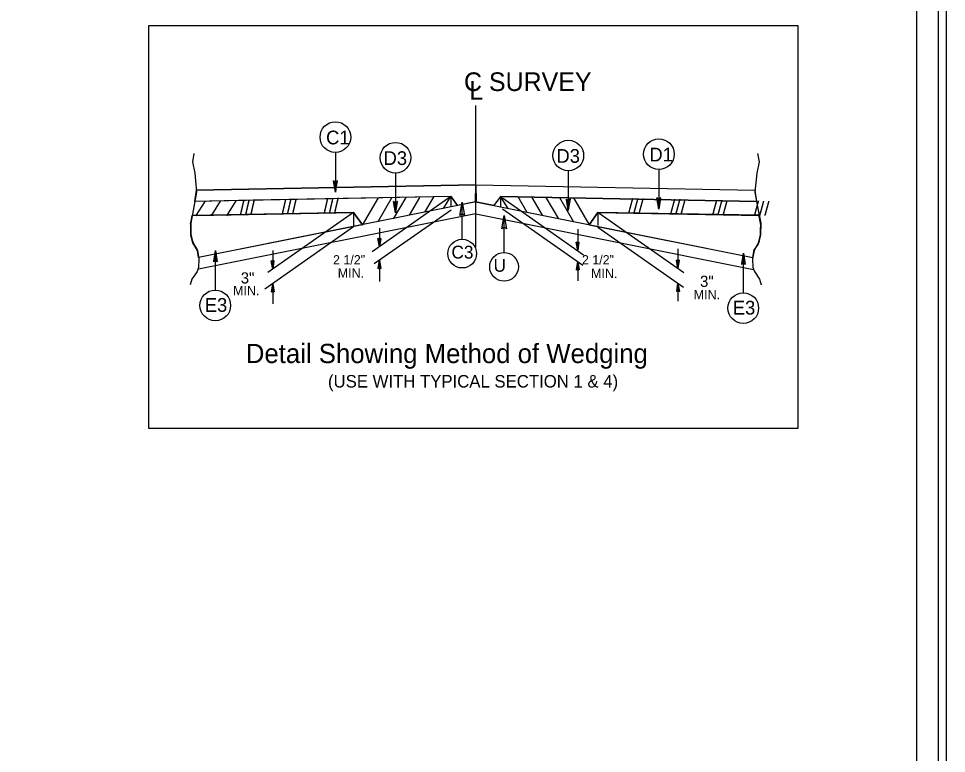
# Model space of a CAD drawing. Extents: x 981824 to 982276, y 44828 to 45204.
# Drawn here: x 982186.38 to 982229.08, y 45122.91 to 45156.74 of the extents above; entities that cross this region are included whole.
import ezdxf

# ---------------------------------------------------------------- set-up
doc = ezdxf.new("R2010")
doc.units = 0
for name, color, linetype in [('Old_Level_1', 7, 'Continuous'), ('Old_Level_11', 7, 'Continuous'), ('Old_Level_18', 7, 'Continuous'), ('Old_Level_19', 7, 'Continuous'), ('Old_Level_2', 7, 'Continuous'), ('Old_Level_20', 7, 'Continuous'), ('Old_Level_21', 7, 'Continuous'), ('Old_Level_3', 7, 'Continuous'), ('Old_Level_50', 7, 'Continuous'), ('Old_Level_51', 7, 'Continuous'), ('Prop Dimension Text', 7, 'Continuous'), ('Prop Roadway Profile Bench Mark Info Text', 7, 'Continuous')]:
    doc.layers.add(name, color=color, linetype=linetype)

msp = doc.modelspace()

# ---------------------------------------------------------------- linework, layer by layer
at = {"layer": 'Old_Level_1'}
for p, q in [((982200.96, 45148.752), (982200.871, 45149.272)), ((982200.96, 45149.201), (982200.871, 45149.272)), ((982200.96, 45148.752), (982200.882, 45149.262)), ((982200.894, 45149.251), (982200.96, 45148.752)), ((982200.96, 45148.752), (982200.909, 45149.24)), ((982200.923, 45149.233), (982200.96, 45148.752)), ((982200.96, 45148.752), (982200.934, 45149.222)), ((982200.948, 45149.213), (982200.96, 45148.752)), ((982200.96, 45148.752), (982201.053, 45149.272)), ((982201.053, 45149.272), (982200.96, 45149.201)), ((982201.035, 45149.262), (982200.96, 45148.752)), ((982200.96, 45148.752), (982201.026, 45149.251)), ((982201.012, 45149.24), (982200.96, 45148.752)), ((982200.96, 45148.752), (982200.997, 45149.233)), ((982200.983, 45149.222), (982200.96, 45148.752)), ((982200.96, 45148.752), (982200.975, 45149.213)), ((982200.96, 45149.201), (982200.96, 45148.752)), ((982194.55, 45147.673), (982194.962, 45148.326)), ((982195.268, 45147.688), (982195.68, 45148.34)), ((982195.962, 45147.661), (982196.399, 45148.354)), ((982202.924, 45148.484), (982202.193, 45147.234)), ((982203.565, 45148.497), (982202.918, 45147.388)), ((982204.2, 45148.51), (982203.62, 45147.515)), ((982203.726, 45147.803), (982203.637, 45148.323)), ((982203.726, 45148.252), (982203.637, 45148.323)), ((982203.726, 45147.803), (982203.648, 45148.313)), ((982203.66, 45148.302), (982203.726, 45147.803)), ((982203.726, 45147.803), (982203.675, 45148.291)), ((982203.689, 45148.284), (982203.726, 45147.803)), ((982203.726, 45147.803), (982203.7, 45148.273)), ((982203.714, 45148.264), (982203.726, 45147.803)), ((982203.726, 45147.803), (982203.819, 45148.323)), ((982203.819, 45148.323), (982203.726, 45148.252)), ((982203.801, 45148.313), (982203.726, 45147.803)), ((982203.726, 45147.803), (982203.792, 45148.302)), ((982203.778, 45148.291), (982203.726, 45147.803)), ((982203.726, 45147.803), (982203.763, 45148.284)), ((982203.749, 45148.273), (982203.726, 45147.803)), ((982203.726, 45147.803), (982203.741, 45148.264)), ((982203.726, 45148.252), (982203.726, 45147.803)), ((982204.839, 45148.508), (982204.358, 45147.684)), ((982205.484, 45148.542), (982205.065, 45147.822)), ((982208.655, 45148.483), (982212.386, 45145.87)), ((982209.357, 45148.542), (982209.776, 45147.822)), ((982210.003, 45148.508), (982210.483, 45147.684)), ((982210.643, 45148.51), (982211.222, 45147.515)), ((982211.277, 45148.497), (982211.923, 45147.388)), ((982211.68, 45147.904), (982211.591, 45148.424)), ((982211.68, 45148.353), (982211.591, 45148.424)), ((982211.68, 45147.904), (982211.602, 45148.414)), ((982211.614, 45148.403), (982211.68, 45147.904)), ((982211.68, 45147.904), (982211.629, 45148.392)), ((982211.643, 45148.385), (982211.68, 45147.904)), ((982211.68, 45147.904), (982211.654, 45148.374)), ((982211.668, 45148.365), (982211.68, 45147.904)), ((982211.68, 45147.904), (982211.773, 45148.424)), ((982211.773, 45148.424), (982211.68, 45148.353)), ((982211.755, 45148.414), (982211.68, 45147.904)), ((982211.68, 45147.904), (982211.746, 45148.403)), ((982211.732, 45148.392), (982211.68, 45147.904)), ((982211.68, 45147.904), (982211.717, 45148.385)), ((982211.703, 45148.374), (982211.68, 45147.904)), ((982211.68, 45147.904), (982211.695, 45148.365)), ((982211.68, 45148.353), (982211.68, 45147.904)), ((982211.919, 45148.484), (982212.638, 45147.251)), ((982215.847, 45147.967), (982215.758, 45148.487)), ((982215.847, 45148.416), (982215.758, 45148.487)), ((982215.847, 45147.967), (982215.769, 45148.477)), ((982215.781, 45148.466), (982215.847, 45147.967)), ((982215.847, 45147.967), (982215.796, 45148.455)), ((982215.81, 45148.448), (982215.847, 45147.967)), ((982215.847, 45147.967), (982215.821, 45148.437)), ((982215.835, 45148.428), (982215.847, 45147.967)), ((982215.847, 45147.967), (982215.94, 45148.487)), ((982215.94, 45148.487), (982215.847, 45148.416)), ((982215.922, 45148.477), (982215.847, 45147.967)), ((982215.847, 45147.967), (982215.913, 45148.466)), ((982215.899, 45148.455), (982215.847, 45147.967)), ((982215.847, 45147.967), (982215.884, 45148.448)), ((982215.87, 45148.437), (982215.847, 45147.967)), ((982215.847, 45147.967), (982215.862, 45148.428)), ((982215.847, 45148.416), (982215.847, 45147.967)), ((982201.799, 45147.818), (982194.373, 45147.67)), ((982194.55, 45147.673), (982201.799, 45147.818)), ((982201.799, 45147.818), (982197.856, 45145.057)), ((982202.204, 45147.25), (982201.799, 45147.818)), ((982201.799, 45147.818), (982201.799, 45147.169)), ((982201.799, 45147.818), (982202.203, 45147.251)), ((982206.287, 45147.923), (982202.744, 45145.442)), ((982208.651, 45147.975), (982212.344, 45145.39)), ((982213.042, 45147.818), (982212.638, 45147.251)), ((982212.639, 45147.251), (982213.042, 45147.818)), ((982213.042, 45147.818), (982220.467, 45147.67)), ((982213.042, 45147.818), (982213.042, 45147.215)), ((982218.339, 45147.712), (982213.042, 45147.818)), ((982213.102, 45147.775), (982216.991, 45145.052)), ((982220.467, 45147.67), (982218.339, 45147.712)), ((982200.507, 45146.912), (982194.668, 45145.745)), ((982201.797, 45147.15), (982197.721, 45144.281)), ((982201.799, 45147.171), (982200.507, 45146.912)), ((982202.203, 45147.251), (982201.799, 45147.171)), ((982202.988, 45147.098), (982202.988, 45146.238)), ((982212.113, 45147.05), (982212.113, 45146.063)), ((982212.638, 45147.251), (982214.335, 45146.912)), ((982213.042, 45147.137), (982216.984, 45144.375)), ((982214.335, 45146.912), (982220.174, 45145.745)), ((982202.988, 45146.238), (982202.922, 45146.615)), ((982202.988, 45146.567), (982202.922, 45146.615)), ((982202.988, 45146.238), (982202.932, 45146.608)), ((982202.941, 45146.602), (982202.988, 45146.238)), ((982202.988, 45146.238), (982202.951, 45146.594)), ((982202.96, 45146.588), (982202.988, 45146.238)), ((982202.988, 45146.238), (982202.969, 45146.58)), ((982202.979, 45146.574), (982202.988, 45146.238)), ((982202.988, 45146.238), (982203.055, 45146.615)), ((982203.055, 45146.615), (982202.988, 45146.567)), ((982203.047, 45146.608), (982202.988, 45146.238)), ((982202.988, 45146.238), (982203.036, 45146.602)), ((982203.027, 45146.594), (982202.988, 45146.238)), ((982202.988, 45146.238), (982203.016, 45146.588)), ((982203.008, 45146.58), (982202.988, 45146.238)), ((982202.988, 45146.238), (982202.998, 45146.574)), ((982202.988, 45146.567), (982202.988, 45146.238)), ((982212.113, 45146.063), (982212.047, 45146.442)), ((982212.113, 45146.391), (982212.047, 45146.442)), ((982212.113, 45146.063), (982212.056, 45146.433)), ((982212.066, 45146.426), (982212.113, 45146.063)), ((982212.113, 45146.063), (982212.181, 45146.442)), ((982212.181, 45146.442), (982212.113, 45146.391)), ((982212.17, 45146.433), (982212.113, 45146.063)), ((982212.113, 45146.063), (982212.159, 45146.426)), ((982195.437, 45146.064), (982195.345, 45145.545)), ((982195.437, 45146.064), (982195.357, 45145.555)), ((982195.37, 45145.567), (982195.437, 45146.064)), ((982195.437, 45146.064), (982195.382, 45145.573)), ((982195.394, 45145.584), (982195.437, 45146.064)), ((982195.437, 45146.064), (982195.409, 45145.591)), ((982195.423, 45145.602), (982195.437, 45146.064)), ((982195.437, 45146.064), (982195.526, 45145.545)), ((982195.512, 45145.555), (982195.437, 45146.064)), ((982195.437, 45146.064), (982195.501, 45145.567)), ((982195.489, 45145.573), (982195.437, 45146.064)), ((982195.437, 45146.064), (982195.475, 45145.584)), ((982195.46, 45145.591), (982195.437, 45146.064)), ((982195.437, 45146.064), (982195.449, 45145.602)), ((982195.437, 45145.613), (982195.437, 45146.064)), ((982198.079, 45146.07), (982198.079, 45145.211)), ((982212.113, 45146.063), (982212.075, 45146.419)), ((982212.085, 45146.413), (982212.113, 45146.063)), ((982212.113, 45146.063), (982212.095, 45146.406)), ((982212.103, 45146.398), (982212.113, 45146.063)), ((982212.15, 45146.419), (982212.113, 45146.063)), ((982212.113, 45146.063), (982212.14, 45146.413)), ((982212.131, 45146.406), (982212.113, 45146.063)), ((982212.113, 45146.063), (982212.123, 45146.398)), ((982212.113, 45146.391), (982212.113, 45146.063)), ((982216.724, 45146.133), (982216.724, 45145.24)), ((982195.437, 45145.613), (982195.345, 45145.545)), ((982195.526, 45145.545), (982195.437, 45145.613)), ((982198.079, 45145.211), (982198.011, 45145.59)), ((982198.079, 45145.54), (982198.011, 45145.59)), ((982198.079, 45145.211), (982198.02, 45145.583)), ((982198.031, 45145.576), (982198.079, 45145.211)), ((982198.079, 45145.211), (982198.041, 45145.569)), ((982198.079, 45145.211), (982198.146, 45145.59)), ((982198.146, 45145.59), (982198.079, 45145.54)), ((982198.136, 45145.583), (982198.079, 45145.211)), ((982198.079, 45145.211), (982198.127, 45145.576)), ((982198.117, 45145.569), (982198.079, 45145.211)), ((982202.988, 45145.614), (982202.922, 45145.234)), ((982202.932, 45145.242), (982202.988, 45145.614)), ((982202.988, 45145.614), (982202.941, 45145.25)), ((982202.951, 45145.257), (982202.988, 45145.614)), ((982202.988, 45145.614), (982202.96, 45145.263)), ((982202.969, 45145.27), (982202.988, 45145.614)), ((982202.988, 45145.614), (982202.979, 45145.276)), ((982202.988, 45145.614), (982202.988, 45144.642)), ((982202.988, 45145.614), (982203.055, 45145.234)), ((982202.988, 45145.285), (982202.988, 45145.614)), ((982202.998, 45145.276), (982202.988, 45145.614)), ((982202.988, 45145.614), (982203.008, 45145.27)), ((982203.016, 45145.263), (982202.988, 45145.614)), ((982202.988, 45145.614), (982203.027, 45145.257)), ((982203.036, 45145.25), (982202.988, 45145.614)), ((982202.988, 45145.614), (982203.047, 45145.242)), ((982216.724, 45145.24), (982216.657, 45145.617)), ((982216.724, 45145.569), (982216.657, 45145.617)), ((982216.724, 45145.24), (982216.666, 45145.61)), ((982216.675, 45145.604), (982216.724, 45145.24)), ((982216.724, 45145.24), (982216.686, 45145.597)), ((982216.694, 45145.59), (982216.724, 45145.24)), ((982216.724, 45145.24), (982216.703, 45145.583)), ((982216.713, 45145.576), (982216.724, 45145.24)), ((982216.724, 45145.24), (982216.791, 45145.617)), ((982216.791, 45145.617), (982216.724, 45145.569)), ((982216.78, 45145.61), (982216.724, 45145.24)), ((982216.724, 45145.24), (982216.771, 45145.604)), ((982216.762, 45145.597), (982216.724, 45145.24)), ((982216.724, 45145.24), (982216.751, 45145.59)), ((982216.743, 45145.583), (982216.724, 45145.24)), ((982216.724, 45145.24), (982216.734, 45145.576)), ((982216.724, 45145.569), (982216.724, 45145.24)), ((982219.735, 45145.939), (982219.643, 45145.42)), ((982219.735, 45145.939), (982219.655, 45145.43)), ((982219.668, 45145.442), (982219.735, 45145.939)), ((982219.735, 45145.939), (982219.68, 45145.448)), ((982219.692, 45145.459), (982219.735, 45145.939)), ((982219.735, 45145.939), (982219.707, 45145.466)), ((982219.721, 45145.477), (982219.735, 45145.939)), ((982219.735, 45145.939), (982219.824, 45145.42)), ((982219.81, 45145.43), (982219.735, 45145.939)), ((982219.735, 45145.939), (982219.799, 45145.442)), ((982219.787, 45145.448), (982219.735, 45145.939)), ((982219.735, 45145.939), (982219.773, 45145.459)), ((982219.758, 45145.466), (982219.735, 45145.939)), ((982219.735, 45145.939), (982219.747, 45145.477)), ((982219.735, 45145.488), (982219.735, 45145.939)), ((982198.051, 45145.562), (982198.079, 45145.211)), ((982198.079, 45145.211), (982198.059, 45145.554)), ((982198.069, 45145.548), (982198.079, 45145.211)), ((982198.079, 45145.211), (982198.107, 45145.562)), ((982198.098, 45145.554), (982198.079, 45145.211)), ((982198.079, 45145.211), (982198.088, 45145.548)), ((982198.079, 45145.54), (982198.079, 45145.211)), ((982202.922, 45145.234), (982202.988, 45145.285)), ((982202.988, 45145.285), (982203.055, 45145.234)), ((982212.113, 45145.553), (982212.047, 45145.174)), ((982212.047, 45145.174), (982212.113, 45145.224)), ((982212.056, 45145.182), (982212.113, 45145.553)), ((982212.113, 45145.553), (982212.066, 45145.188)), ((982212.075, 45145.196), (982212.113, 45145.553)), ((982212.113, 45145.553), (982212.085, 45145.201)), ((982212.095, 45145.209), (982212.113, 45145.553)), ((982212.113, 45145.553), (982212.103, 45145.216)), ((982212.113, 45145.553), (982212.113, 45144.669)), ((982212.113, 45145.553), (982212.181, 45145.174)), ((982212.113, 45145.224), (982212.113, 45145.553)), ((982212.123, 45145.216), (982212.113, 45145.553)), ((982212.113, 45145.553), (982212.131, 45145.209)), ((982212.14, 45145.201), (982212.113, 45145.553)), ((982212.113, 45145.553), (982212.15, 45145.196)), ((982212.159, 45145.188), (982212.113, 45145.553)), ((982212.113, 45145.553), (982212.17, 45145.182)), ((982212.113, 45145.224), (982212.181, 45145.174)), ((982219.735, 45145.488), (982219.643, 45145.42)), ((982219.824, 45145.42), (982219.735, 45145.488)), ((982198.079, 45144.532), (982198.011, 45144.155)), ((982198.022, 45144.161), (982198.079, 45144.532)), ((982198.079, 45144.532), (982198.031, 45144.169)), ((982198.041, 45144.175), (982198.079, 45144.532)), ((982198.079, 45144.532), (982198.051, 45144.183)), ((982198.059, 45144.189), (982198.079, 45144.532)), ((982198.079, 45144.532), (982198.069, 45144.196)), ((982198.079, 45144.532), (982198.079, 45143.614)), ((982198.079, 45144.532), (982198.146, 45144.155)), ((982198.079, 45144.202), (982198.079, 45144.532)), ((982198.088, 45144.196), (982198.079, 45144.532)), ((982198.079, 45144.532), (982198.098, 45144.189)), ((982198.107, 45144.183), (982198.079, 45144.532)), ((982198.079, 45144.532), (982198.117, 45144.175)), ((982198.127, 45144.169), (982198.079, 45144.532)), ((982198.079, 45144.532), (982198.136, 45144.161)), ((982216.724, 45144.558), (982216.657, 45144.18)), ((982216.666, 45144.186), (982216.724, 45144.558)), ((982216.724, 45144.558), (982216.675, 45144.194)), ((982216.686, 45144.201), (982216.724, 45144.558)), ((982216.724, 45144.558), (982216.694, 45144.21)), ((982216.703, 45144.215), (982216.724, 45144.558)), ((982216.724, 45144.558), (982216.713, 45144.222)), ((982216.724, 45144.558), (982216.724, 45143.73)), ((982216.724, 45144.558), (982216.791, 45144.18)), ((982216.724, 45144.23), (982216.724, 45144.558)), ((982216.734, 45144.222), (982216.724, 45144.558)), ((982216.724, 45144.558), (982216.743, 45144.215)), ((982216.751, 45144.21), (982216.724, 45144.558)), ((982216.724, 45144.558), (982216.762, 45144.201)), ((982216.771, 45144.194), (982216.724, 45144.558)), ((982216.724, 45144.558), (982216.78, 45144.186)), ((982198.011, 45144.155), (982198.079, 45144.202)), ((982198.079, 45144.202), (982198.146, 45144.155)), ((982216.657, 45144.18), (982216.724, 45144.23)), ((982216.724, 45144.23), (982216.791, 45144.18))]:
    msp.add_line(p, q, dxfattribs=at)
for points in [[(982194.668, 45145.745), (982194.612, 45146.059), (982194.406, 45146.414), (982194.316, 45146.767), (982194.305, 45147.326), (982194.373, 45147.67)], [(982220.174, 45145.745), (982220.23, 45146.059), (982220.435, 45146.414), (982220.527, 45146.767), (982220.537, 45147.326), (982220.467, 45147.67)]]:
    msp.add_lwpolyline(points, dxfattribs=at)
at = {"layer": 'Old_Level_11'}
for p, q in [((982194.572, 45148.833), (982207.42, 45149.089)), ((982207.42, 45149.089), (982220.27, 45148.833)), ((982207.422, 45149.089), (982220.27, 45148.833)), ((982220.27, 45148.833), (982220.344, 45148.316)), ((982206.293, 45148.551), (982194.499, 45148.316)), ((982206.582, 45148.129), (982206.293, 45148.551)), ((982207.402, 45148.298), (982206.582, 45148.129)), ((982208.26, 45148.129), (982207.402, 45148.298)), ((982208.557, 45148.551), (982208.26, 45148.129)), ((982208.557, 45148.551), (982220.344, 45148.316))]:
    msp.add_line(p, q, dxfattribs=at)
for points in [[(982192.377, 45156.415), (982222.235, 45156.415), (982222.235, 45137.875), (982192.377, 45137.875)], [(982206.692, 45147.677), (982206.798, 45148.289), (982206.907, 45147.673), (982206.798, 45147.751)], [(982208.619, 45147.068), (982208.724, 45147.68), (982208.833, 45147.064), (982208.724, 45147.142)]]:
    msp.add_lwpolyline(points, close=True, dxfattribs=at)
at = {"layer": 'Old_Level_18'}
msp.add_lwpolyline([(982227.72, 45175.969), (982107.72, 45175.969), (982107.72, 45091.969), (982227.72, 45091.969)], close=True, dxfattribs=at)
at = {"layer": 'Old_Level_19'}
for points in [[(982194.572, 45148.833), (982207.42, 45149.089), (982207.439, 45148.298), (982206.582, 45148.129), (982206.293, 45148.551), (982197.172, 45148.374), (982194.499, 45148.316)], [(982207.42, 45149.089), (982220.27, 45148.833), (982220.344, 45148.316), (982208.557, 45148.551), (982208.26, 45148.129), (982207.402, 45148.298)]]:
    msp.add_lwpolyline(points, close=True, dxfattribs=at)
at = {"layer": 'Old_Level_2'}
for p, q in [((982200.96, 45150.58), (982200.96, 45148.752)), ((982203.726, 45149.631), (982203.726, 45147.803)), ((982211.68, 45149.732), (982211.68, 45147.904)), ((982215.847, 45149.795), (982215.847, 45147.967)), ((982195.437, 45144.237), (982195.437, 45146.064)), ((982219.735, 45144.112), (982219.735, 45145.939))]:
    msp.add_line(p, q, dxfattribs=at)
for centre in [(982200.96, 45151.283), (982211.68, 45150.435), (982215.847, 45150.498), (982203.726, 45150.334), (982195.435, 45143.534), (982219.732, 45143.409)]:
    msp.add_circle(centre, 0.706, dxfattribs=at)
at = {"layer": 'Old_Level_3'}
for points in [[(982194.373, 45147.67), (982201.799, 45147.818), (982202.203, 45147.251), (982194.668, 45145.745), (982194.654, 45145.974), (982194.579, 45146.15), (982194.45, 45146.372), (982194.394, 45146.494), (982194.357, 45146.67), (982194.329, 45146.818), (982194.319, 45146.929), (982194.319, 45147.022), (982194.319, 45147.142), (982194.301, 45147.31), (982194.375, 45147.56)], [(982212.638, 45147.251), (982220.174, 45145.745), (982220.203, 45145.918), (982220.239, 45146.086), (982220.304, 45146.178), (982220.415, 45146.346), (982220.471, 45146.503), (982220.49, 45146.642), (982220.518, 45146.754), (982220.537, 45146.921), (982220.518, 45147.088), (982220.537, 45147.19), (982220.518, 45147.338), (982220.499, 45147.469), (982220.471, 45147.589), (982220.453, 45147.663), (982220.453, 45147.682), (982213.042, 45147.818)]]:
    msp.add_lwpolyline(points, close=True, dxfattribs=at)
at = {"layer": 'Old_Level_50'}
msp.add_lwpolyline([(982228.72, 45176.173), (982095.4, 45176.173), (982095.4, 45091.765), (982228.72, 45091.765)], close=True, dxfattribs=at)
at = {"layer": 'Old_Level_51'}
msp.add_lwpolyline([(982229.08, 45177.969), (982094.36, 45177.969), (982094.36, 45089.969), (982229.08, 45089.969)], close=True, dxfattribs=at)
at = {"layer": 'Prop Dimension Text'}
for p, q in [((982207.42, 45146.197), (982207.42, 45152.744)), ((982207.42, 45146.197), (982207.42, 45150.668)), ((982207.42, 45149.089), (982194.572, 45148.833)), ((982206.293, 45148.551), (982194.499, 45148.316)), ((982207.439, 45148.298), (982194.668, 45145.745)), ((982206.279, 45148.542), (982202.658, 45146.007)), ((982205.929, 45148.002), (982206.278, 45148.547)), ((982206.278, 45148.547), (982206.278, 45148.099)), ((982206.293, 45148.538), (982206.582, 45148.129)), ((982206.798, 45146.58), (982206.798, 45148.289)), ((982207.402, 45148.298), (982220.174, 45145.745)), ((982208.557, 45148.551), (982208.26, 45148.129)), ((982208.539, 45148.542), (982208.556, 45148.542)), ((982208.913, 45148.002), (982208.566, 45148.547)), ((982208.566, 45148.547), (982208.566, 45148.053)), ((982208.724, 45145.971), (982208.724, 45147.68))]:
    msp.add_line(p, q, dxfattribs=at)
for centre in [(982206.797, 45145.92), (982208.723, 45145.311)]:
    msp.add_circle(centre, 0.661, dxfattribs=at)
at = {"layer": 'Prop Roadway Profile Bench Mark Info Text'}
for p, q in [((982207.415, 45147.749), (982194.663, 45145.198)), ((982207.425, 45147.749), (982220.207, 45145.194))]:
    msp.add_line(p, q, dxfattribs=at)
for points in [[(982194.451, 45150.529), (982194.383, 45150.151), (982194.487, 45149.617), (982194.576, 45148.75), (982194.451, 45148.067), (982194.305, 45147.326), (982194.316, 45146.767), (982194.406, 45146.414), (982194.612, 45146.059), (982194.68, 45145.672), (982194.669, 45145.286), (982194.601, 45145.102), (982194.361, 45144.738), (982194.281, 45144.487)], [(982220.389, 45150.529), (982220.459, 45150.151), (982220.355, 45149.617), (982220.263, 45148.75), (982220.389, 45148.067), (982220.537, 45147.326), (982220.527, 45146.767), (982220.435, 45146.414), (982220.23, 45146.059), (982220.162, 45145.672), (982220.173, 45145.286), (982220.241, 45145.102), (982220.479, 45144.738), (982220.561, 45144.487)]]:
    msp.add_lwpolyline(points, dxfattribs=at)

# ---------------------------------------------------------------- texts
at = {"layer": 'Old_Level_1'}
for s, height, p in [('C SURVEY ', 0.8585, (982206.879, 45153.405)), ('L', 0.858, (982207.128, 45153.005)), ('(USE WITH TYPICAL SECTION 1 & 4)', 0.576, (982200.62, 45139.754))]:
    msp.add_text(s, height=height, dxfattribs=at).set_placement(p)
for height, rotation, p in [(0.6443, 1.1464, (982196.556, 45147.7)), (0.644, 1.1445, (982198.486, 45147.758)), (0.6441, 1.1463, (982200.417, 45147.798)), (0.6441, 358.8553, (982214.425, 45147.798)), (0.6441, 358.8536, (982216.357, 45147.758)), (0.6443, 358.8554, (982218.287, 45147.7)), (0.6443, 358.8537, (982220.212, 45147.679))]:
    msp.add_text('/// ', height=height, rotation=rotation, dxfattribs=at).set_placement(p)
at = {"layer": 'Old_Level_20'}
for s, height, p in [('C1', 0.6316, (982200.534, 45150.949)), ('D3', 0.6316, (982211.134, 45150.101)), ('D1', 0.6316, (982215.412, 45150.164)), ('D3', 0.6316, (982203.18, 45150)), ('C3', 0.5916, (982206.303, 45145.693)), (' 2 1/2"', 0.4282, (982200.693, 45145.42)), ('U ', 0.5916, (982208.239, 45145.084)), (' 2 1/2"', 0.4282, (982212.147, 45145.42)), ('3" ', 0.5137, (982196.607, 45144.543)), ('3" ', 0.5137, (982217.742, 45144.386)), ('E3', 0.6316, (982194.952, 45143.239)), ('E3', 0.6316, (982219.25, 45143.114))]:
    msp.add_text(s, height=height, dxfattribs=at).set_placement(p)
at = {"layer": 'Old_Level_21'}
for s, height, p in [('MIN.', 0.4292, (982201.071, 45144.811)), ('MIN.', 0.4292, (982212.727, 45144.797)), ('MIN.', 0.4292, (982196.253, 45144.005)), ('MIN.', 0.4292, (982217.45, 45143.818)), ('Detail Showing Method of Wedging', 0.88568, (982196.84, 45140.88))]:
    msp.add_text(s, height=height, dxfattribs=at).set_placement(p)

doc.saveas('drawing.dxf')
